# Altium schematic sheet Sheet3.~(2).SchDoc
size A4
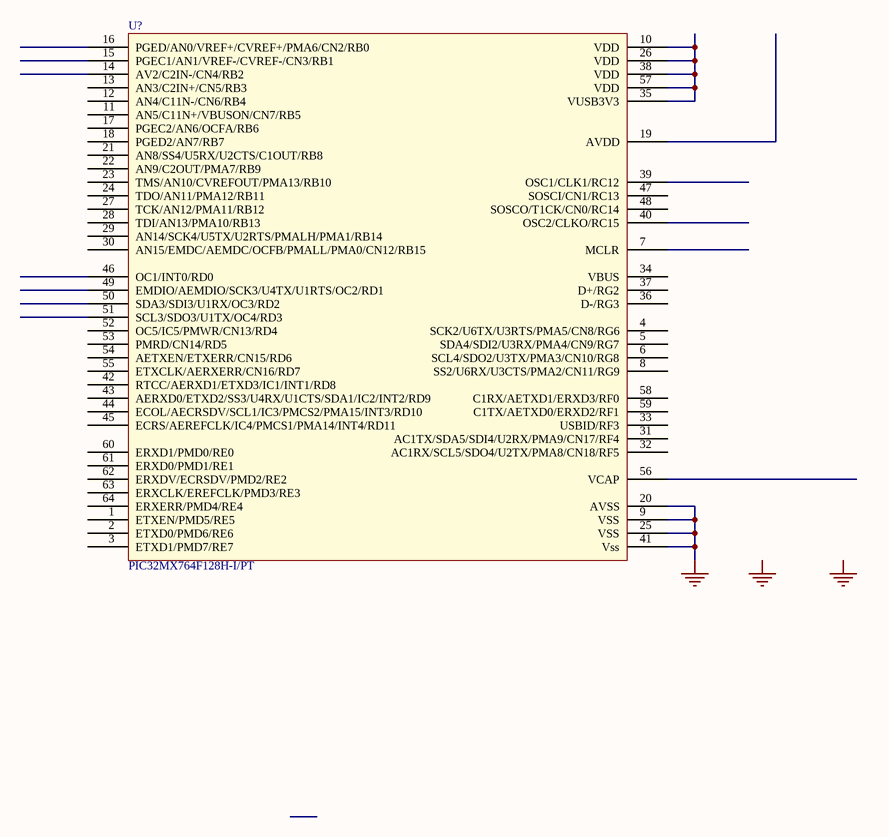
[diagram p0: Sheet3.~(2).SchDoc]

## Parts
U?  PIC32MX764F128H-I/PT

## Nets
GND: U?.9(VSS) U?.20(AVSS) U?.25(VSS) U?.41(Vss)
NetU?_10: U?.10(VDD) U?.26(VDD) U?.35(VUSB3V3) U?.38(VDD) U?.57(VDD)

Not connected (* = marked no-connect by the designer): U? 1(ETXEN/PMD5/RE5) 2(ETXD0/PMD6/RE6) 3(ETXD1/PMD7/RE7) 4(SCK2/U6TX/U3RTS/PMA5/CN8/RG6) 5(SDA4/SDI2/U3RX/PMA4/CN9/RG7) 6(SCL4/SDO2/U3TX/PMA3/CN10/RG8) 7(MCLR) 8(SS2/U6RX/U3CTS/PMA2/CN11/RG9) 11(AN5/C11N+/VBUSON/CN7/RB5) 12(AN4/C11N-/CN6/RB4) 13(AN3/C2IN+/CN5/RB3) 14(AV2/C2IN-/CN4/RB2) 15(PGEC1/AN1/VREF-/CVREF-/CN3/RB1) 16(PGED/AN0/VREF+/CVREF+/PMA6/CN2/RB0) 17(PGEC2/AN6/OCFA/RB6) 18(PGED2/AN7/RB7) 19(AVDD) 21(AN8/SS4/U5RX/U2CTS/C1OUT/RB8) 22(AN9/C2OUT/PMA7/RB9) 23(TMS/AN10/CVREFOUT/PMA13/RB10) 24(TDO/AN11/PMA12/RB11) 27(TCK/AN12/PMA11/RB12) 28(TDI/AN13/PMA10/RB13) 29(AN14/SCK4/U5TX/U2RTS/PMALH/PMA1/RB14) 30(AN15/EMDC/AEMDC/OCFB/PMALL/PMA0/CN12/RB15) 31(AC1TX/SDA5/SDI4/U2RX/PMA9/CN17/RF4) 32(AC1RX/SCL5/SDO4/U2TX/PMA8/CN18/RF5) 33(USBID/RF3) 34(VBUS) 36(D-/RG3) 37(D+/RG2) 39(OSC1/CLK1/RC12) 40(OSC2/CLKO/RC15) 42(RTCC/AERXD1/ETXD3/IC1/INT1/RD8) 43(AERXD0/ETXD2/SS3/U4RX/U1CTS/SDA1/IC2/INT2/RD9) 44(ECOL/AECRSDV/SCL1/IC3/PMCS2/PMA15/INT3/RD10) 45(ECRS/AEREFCLK/IC4/PMCS1/PMA14/INT4/RD11) 46(OC1/INT0/RD0) 47(SOSCI/CN1/RC13) 48(SOSCO/T1CK/CN0/RC14) 49(EMDIO/AEMDIO/SCK3/U4TX/U1RTS/OC2/RD1) 50(SDA3/SDI3/U1RX/OC3/RD2) 51(SCL3/SDO3/U1TX/OC4/RD3) 52(OC5/IC5/PMWR/CN13/RD4) 53(PMRD/CN14/RD5) 54(AETXEN/ETXERR/CN15/RD6) 55(ETXCLK/AERXERR/CN16/RD7) 56(VCAP) 58(C1RX/AETXD1/ERXD3/RF0) 59(C1TX/AETXD0/ERXD2/RF1) 60(ERXD1/PMD0/RE0) 61(ERXD0/PMD1/RE1) 62(ERXDV/ECRSDV/PMD2/RE2) 63(ERXCLK/EREFCLK/PMD3/RE3) 64(ERXERR/PMD4/RE4)

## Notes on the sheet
- Labels drawn without touching a wire or pin: GND

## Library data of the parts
U? = PIC32MX764F128H-I/PT: Fabricant: Microchip; Fournisseur: Farnell; RefFournisseur: 1971889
